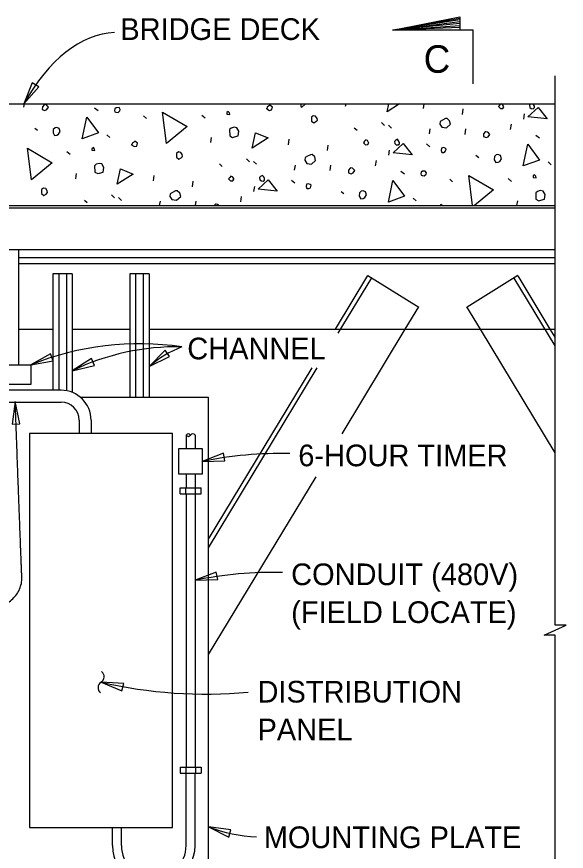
# Model space of a CAD drawing. Extents: x 927736.2 to 927809.6, y 636703.6 to 636757.7.
# Drawn here: x 927764.73 to 927774.19, y 636743.33 to 636757.7 of the extents above; entities that cross this region are included whole.
import ezdxf

# ---------------------------------------------------------------- set-up
doc = ezdxf.new("R2010")
doc.units = 0
for name, color, linetype in [('DimLines_dp', 7, 'Continuous'), ('Miscellaneous1', 7, 'Continuous'), ('Miscellaneous2', 7, 'Continuous'), ('Miscellaneous3', 7, 'Continuous')]:
    doc.layers.add(name, color=color, linetype=linetype)

msp = doc.modelspace()

# ---------------------------------------------------------------- linework, layer by layer
at = {"layer": 'DimLines_dp'}
for p, q in [((927771.201, 636757.464), (927772.357, 636757.668)), ((927772.357, 636757.643), (927771.201, 636757.464)), ((927771.201, 636757.464), (927772.357, 636757.612)), ((927772.357, 636757.578), (927771.201, 636757.464)), ((927771.201, 636757.464), (927772.357, 636757.544)), ((927772.357, 636757.507), (927771.201, 636757.464))]:
    msp.add_line(p, q, dxfattribs=at)
for points in [[(927772.589, 636756.539), (927772.589, 636757.464), (927771.201, 636757.464), (927772.357, 636757.695), (927772.357, 636757.464)], [(927774, 636737.782), (927774, 636747.055), (927773.809, 636747.055), (927774, 636747.139), (927774.191, 636747.222), (927774, 636747.222), (927774, 636756.677)]]:
    msp.add_lwpolyline(points, dxfattribs=at)
for points in [[(927764.852, 636756.193), (927765.11, 636756.486), (927764.999, 636756.555)], [(927764.974, 636751.702), (927765.359, 636751.771), (927765.315, 636751.894)], [(927767.01, 636751.678), (927767.362, 636751.848), (927767.286, 636751.954)], [(927765.688, 636751.603), (927766.068, 636751.693), (927766.018, 636751.813)], [(927764.705, 636751.071), (927764.654, 636750.684), (927764.785, 636750.688)], [(927767.924, 636750.042), (927768.314, 636750.055), (927768.288, 636750.183)], [(927767.801, 636747.996), (927768.191, 636748.009), (927768.165, 636748.137)], [(927766.183, 636746.244), (927766.543, 636746.093), (927766.573, 636746.221)], [(927768.032, 636743.756), (927768.38, 636743.579), (927768.419, 636743.703)]]:
    msp.add_lwpolyline(points, close=True, dxfattribs=at)
for centre, radius, start, end in [((927766.848, 636747.067), 5, 81.6635, 112.0069), ((927767.492, 636747.853), 4.162, 88.8828, 115.6789), ((927768.324, 636750.113), 2.043, 111.5678, 130.0212), ((927769.285, 636743.338), 6.841, 88.7814, 101.4782), ((927769.162, 636741.292), 6.841, 88.7814, 101.4782), ((927766.126, 636746.337), 0.11, 301.142, 52.8692), ((927766.24, 636746.148), 0.11, 121.142, 232.8692), ((927767.974, 636753.978), 7.939, 256.9627, 275.3449), ((927768.996, 636746.243), 2.667, 248.8193, 267.0903)]:
    msp.add_arc(centre, radius, start, end, dxfattribs=at)
msp.add_ellipse((927766.69, 636751.583), major_axis=(0.274, -5.84), ratio=0.464296, start_param=3.141604, end_param=3.781059, dxfattribs=at)
msp.add_open_spline([(927758.883, 636747.305), (927762.516, 636747.33), (927764.844, 636747.456), (927764.793, 636748.678), (927764.705, 636751.071)], degree=2, dxfattribs=at)
at = {"layer": 'Miscellaneous1'}
for p, q in [((927765.354, 636753.27), (927765.354, 636751.267)), ((927765.688, 636753.27), (927765.354, 636753.27)), ((927765.457, 636753.27), (927765.457, 636751.267)), ((927765.586, 636753.27), (927765.586, 636751.259)), ((927765.688, 636753.27), (927765.688, 636751.23)), ((927767.01, 636753.27), (927766.676, 636753.27)), ((927766.676, 636753.27), (927766.676, 636751.141)), ((927766.778, 636753.27), (927766.778, 636751.141)), ((927766.907, 636753.27), (927766.907, 636751.141)), ((927767.01, 636753.27), (927767.01, 636751.141)), ((927763.253, 636751.702), (927764.974, 636751.702)), ((927764.974, 636751.702), (927764.974, 636751.368)), ((927764.974, 636751.368), (927764.014, 636751.368)), ((927765.497, 636751.267), (927764.242, 636751.267)), ((927764.242, 636751.062), (927765.497, 636751.061)), ((927765.805, 636750.753), (927765.805, 636750.524)), ((927766.011, 636750.753), (927766.011, 636750.524)), ((927767.646, 636750.497), (927767.646, 636750.262)), ((927767.801, 636750.497), (927767.801, 636750.262)), ((927767.646, 636749.822), (927767.646, 636749.588)), ((927767.801, 636749.822), (927767.801, 636749.588)), ((927767.646, 636749.485), (927767.646, 636744.78)), ((927767.801, 636749.485), (927767.801, 636744.78)), ((927767.646, 636743.432), (927767.646, 636744.677)), ((927767.801, 636743.432), (927767.801, 636744.677)), ((927766.379, 636743.432), (927766.379, 636743.741)), ((927766.533, 636743.432), (927766.533, 636743.741))]:
    msp.add_line(p, q, dxfattribs=at)
for points in [[(927767.415, 636750.524), (927764.949, 636750.524), (927764.949, 636743.741), (927767.415, 636743.741)], [(927767.524, 636750.262), (927767.924, 636750.262), (927767.924, 636749.822), (927767.524, 636749.822)]]:
    msp.add_lwpolyline(points, close=True, dxfattribs=at)
for centre, radius, start, end in [((927765.497, 636750.753), 0.514, 0, 89.9792), ((927765.497, 636750.753), 0.308, 0, 89.9792), ((927767.685, 636750.475), 0.0441, 29.0027, 150.9974), ((927767.685, 636750.518), 0.0441, 209.003, 330.9971), ((927767.762, 636750.475), 0.0441, 29.0028, 150.9973), ((927767.09, 636743.432), 0.711, 179.9955, 0.0001), ((927767.09, 636743.432), 0.557, 180, 0)]:
    msp.add_arc(centre, radius, start, end, dxfattribs=at)
at = {"layer": 'Miscellaneous2'}
for p, q in [((927753.063, 636756.193), (927774, 636756.193)), ((927764.855, 636756.138), (927764.863, 636756.193)), ((927770.393, 636756.153), (927770.399, 636756.193)), ((927771.731, 636756.116), (927771.742, 636756.193)), ((927766.072, 636756.125), (927766.135, 636756.079)), ((927767.918, 636756.001), (927767.976, 636755.953)), ((927772.402, 636756.015), (927772.416, 636756.108)), ((927773.458, 636755.934), (927773.473, 636756.021)), ((927766.913, 636755.987), (927766.963, 636755.943)), ((927771.011, 636755.872), (927771.062, 636755.822)), ((927765.041, 636755.779), (927765.089, 636755.741)), ((927770.542, 636755.785), (927770.593, 636755.741)), ((927771.131, 636755.828), (927771.183, 636755.778)), ((927771.835, 636755.678), (927771.85, 636755.765)), ((927772.45, 636755.67), (927772.463, 636755.763)), ((927773.232, 636755.752), (927773.246, 636755.845)), ((927766.284, 636755.665), (927766.336, 636755.615)), ((927768.07, 636755.531), (927768.085, 636755.618)), ((927769.407, 636755.493), (927769.421, 636755.586)), ((927773.666, 636755.658), (927773.73, 636755.611)), ((927770.079, 636755.393), (927770.093, 636755.486)), ((927771.786, 636755.505), (927771.843, 636755.457)), ((927765.595, 636755.378), (927765.653, 636755.33)), ((927771.135, 636755.312), (927771.15, 636755.399)), ((927772.636, 636755.311), (927772.684, 636755.273)), ((927768.219, 636755.162), (927768.269, 636755.118)), ((927768.688, 636755.249), (927768.739, 636755.2)), ((927768.808, 636755.205), (927768.86, 636755.155)), ((927769.512, 636755.055), (927769.527, 636755.142)), ((927770.127, 636755.048), (927770.14, 636755.141)), ((927770.909, 636755.13), (927770.923, 636755.223)), ((927773.879, 636755.198), (927773.931, 636755.148)), ((927765.747, 636754.908), (927765.762, 636754.995)), ((927771.343, 636755.035), (927771.407, 636754.989)), ((927767.084, 636754.871), (927767.098, 636754.964)), ((927767.756, 636754.77), (927767.77, 636754.863)), ((927769.463, 636754.883), (927769.52, 636754.834)), ((927772.185, 636754.897), (927772.235, 636754.853)), ((927773.19, 636754.911), (927773.247, 636754.862)), ((927768.812, 636754.689), (927768.827, 636754.776)), ((927766.365, 636754.627), (927766.416, 636754.577)), ((927766.485, 636754.583), (927766.537, 636754.533)), ((927768.586, 636754.507), (927768.6, 636754.6)), ((927770.313, 636754.689), (927770.361, 636754.651)), ((927771.556, 636754.575), (927771.608, 636754.525)), ((927762.11, 636754.446), (927774, 636754.446)), ((927765.896, 636754.54), (927765.946, 636754.496)), ((927767.191, 636754.446), (927767.204, 636754.52)), ((927767.807, 636754.446), (927767.817, 636754.518)), ((927773.342, 636754.446), (927773.356, 636754.528)), ((927762.121, 636754.407), (927774, 636754.407)), ((927760.453, 636753.688), (927774, 636753.688))]:
    msp.add_line(p, q, dxfattribs=at)
for points in [[(927765.172, 636756.146), (927765.171, 636756.101), (927765.215, 636756.081), (927765.249, 636756.097), (927765.277, 636756.136), (927765.257, 636756.163), (927765.241, 636756.177), (927765.213, 636756.183), (927765.202, 636756.18), (927765.172, 636756.146)], [(927769.038, 636756.11), (927769.083, 636756.083), (927769.119, 636756.093), (927769.132, 636756.141), (927769.085, 636756.173), (927769.064, 636756.155), (927769.042, 636756.142), (927769.038, 636756.11), (927769.035, 636756.121)], [(927769.632, 636756.134), (927769.624, 636756.193)], [(927769.702, 636756.193), (927769.632, 636756.134)], [(927771.108, 636756.058), (927771.137, 636756.193)], [(927771.318, 636756.193), (927771.108, 636756.058)], [(927773.024, 636756.15), (927773.059, 636756.114), (927773.096, 636756.118), (927773.115, 636756.142), (927773.112, 636756.154), (927773.091, 636756.187), (927773.075, 636756.193)], [(927773.058, 636756.193), (927773.043, 636756.174), (927773.024, 636756.15)], [(927773.581, 636756.193), (927773.575, 636756.189), (927773.555, 636756.171), (927773.564, 636756.135)], [(927773.564, 636756.135), (927773.588, 636756.116), (927773.621, 636756.112), (927773.642, 636756.13), (927773.642, 636756.156), (927773.628, 636756.184), (927773.621, 636756.193)], [(927766.421, 636756.06), (927766.436, 636756.051), (927766.475, 636756.048), (927766.506, 636756.076), (927766.513, 636756.097), (927766.492, 636756.13), (927766.441, 636756.129), (927766.42, 636756.11), (927766.415, 636756.083), (927766.421, 636756.06)], [(927767.308, 636755.512), (927767.24, 636756.055), (927767.664, 636755.805), (927767.308, 636755.512)], [(927768.347, 636756.02), (927768.399, 636756.015), (927768.393, 636756.039), (927768.373, 636756.065), (927768.347, 636756.046), (927768.347, 636756.02)], [(927773.531, 636755.973), (927773.705, 636756.134), (927773.859, 636755.939), (927773.531, 636755.973)], [(927765.856, 636755.595), (927765.935, 636755.968), (927766.136, 636755.696), (927765.856, 636755.595)], [(927769.804, 636755.944), (927769.803, 636755.9), (927769.844, 636755.866), (927769.882, 636755.889), (927769.907, 636755.915), (927769.9, 636755.945), (927769.876, 636755.983), (927769.836, 636755.991), (927769.805, 636755.964), (927769.804, 636755.944)], [(927772.013, 636755.847), (927772.047, 636755.792), (927772.127, 636755.782), (927772.199, 636755.846), (927772.183, 636755.905), (927772.14, 636755.945), (927772.109, 636755.943), (927772.058, 636755.917), (927772.02, 636755.893), (927772.013, 636755.847)], [(927765.36, 636755.756), (927765.356, 636755.698), (927765.381, 636755.653), (927765.424, 636755.658), (927765.452, 636755.672), (927765.479, 636755.718), (927765.464, 636755.771), (927765.421, 636755.791), (927765.391, 636755.783), (927765.36, 636755.756)], [(927768.393, 636755.752), (927768.397, 636755.644), (927768.448, 636755.619), (927768.478, 636755.627), (927768.543, 636755.645), (927768.554, 636755.724), (927768.519, 636755.785), (927768.472, 636755.792), (927768.424, 636755.779), (927768.393, 636755.752)], [(927772.767, 636755.679), (927772.766, 636755.634), (927772.81, 636755.614), (927772.844, 636755.629), (927772.872, 636755.668), (927772.852, 636755.695), (927772.835, 636755.71), (927772.808, 636755.715), (927772.796, 636755.712), (927772.767, 636755.679)], [(927768.785, 636755.435), (927768.842, 636755.699), (927769.057, 636755.61), (927768.785, 636755.435)], [(927770.701, 636755.527), (927770.736, 636755.492), (927770.773, 636755.495), (927770.792, 636755.52), (927770.789, 636755.532), (927770.768, 636755.564), (927770.739, 636755.576), (927770.72, 636755.551), (927770.701, 636755.527)], [(927771.241, 636755.512), (927771.265, 636755.493), (927771.298, 636755.489), (927771.319, 636755.508), (927771.319, 636755.533), (927771.305, 636755.561), (927771.285, 636755.588), (927771.252, 636755.566), (927771.231, 636755.548), (927771.241, 636755.512)], [(927764.985, 636754.89), (927764.916, 636755.433), (927765.341, 636755.183), (927764.985, 636754.89)], [(927766.024, 636755.398), (927766.076, 636755.393), (927766.07, 636755.416), (927766.05, 636755.443), (927766.024, 636755.423), (927766.024, 636755.398)], [(927766.715, 636755.487), (927766.76, 636755.461), (927766.796, 636755.47), (927766.809, 636755.519), (927766.762, 636755.551), (927766.741, 636755.532), (927766.719, 636755.52), (927766.715, 636755.487), (927766.712, 636755.499)], [(927771.208, 636755.35), (927771.382, 636755.512), (927771.536, 636755.317), (927771.208, 636755.35)], [(927772.039, 636755.394), (927772.048, 636755.358), (927772.08, 636755.36), (927772.108, 636755.374), (927772.122, 636755.416), (927772.106, 636755.431), (927772.077, 636755.443), (927772.041, 636755.433), (927772.039, 636755.394)], [(927773.451, 636755.128), (927773.53, 636755.5), (927773.73, 636755.228), (927773.451, 636755.128)], [(927767.481, 636755.322), (927767.48, 636755.277), (927767.521, 636755.243), (927767.559, 636755.266), (927767.584, 636755.292), (927767.576, 636755.322), (927767.553, 636755.361), (927767.513, 636755.369), (927767.482, 636755.341), (927767.481, 636755.322)], [(927769.69, 636755.224), (927769.724, 636755.17), (927769.804, 636755.159), (927769.876, 636755.223), (927769.86, 636755.283), (927769.817, 636755.322), (927769.786, 636755.32), (927769.735, 636755.294), (927769.697, 636755.271), (927769.69, 636755.224)], [(927772.955, 636755.288), (927772.951, 636755.23), (927772.976, 636755.186), (927773.019, 636755.191), (927773.047, 636755.205), (927773.073, 636755.25), (927773.059, 636755.304), (927773.015, 636755.324), (927772.986, 636755.316), (927772.955, 636755.288)], [(927766.07, 636755.129), (927766.074, 636755.022), (927766.125, 636754.997), (927766.155, 636755.005), (927766.22, 636755.022), (927766.231, 636755.102), (927766.195, 636755.163), (927766.149, 636755.169), (927766.101, 636755.157), (927766.07, 636755.129)], [(927766.462, 636754.813), (927766.519, 636755.077), (927766.734, 636754.988), (927766.462, 636754.813)], [(927770.444, 636755.056), (927770.443, 636755.011), (927770.487, 636754.991), (927770.521, 636755.007), (927770.549, 636755.046), (927770.529, 636755.073), (927770.512, 636755.087), (927770.485, 636755.093), (927770.473, 636755.09), (927770.444, 636755.056)], [(927771.693, 636754.969), (927771.708, 636754.961), (927771.747, 636754.958), (927771.778, 636754.986), (927771.785, 636755.007), (927771.764, 636755.039), (927771.713, 636755.039), (927771.692, 636755.02), (927771.687, 636754.993), (927771.693, 636754.969)], [(927768.378, 636754.905), (927768.413, 636754.869), (927768.45, 636754.873), (927768.469, 636754.897), (927768.466, 636754.909), (927768.444, 636754.942), (927768.416, 636754.953), (927768.397, 636754.929), (927768.378, 636754.905)], [(927768.885, 636754.728), (927769.059, 636754.889), (927769.213, 636754.694), (927768.885, 636754.728)], [(927768.918, 636754.89), (927768.942, 636754.871), (927768.975, 636754.867), (927768.996, 636754.885), (927768.995, 636754.911), (927768.982, 636754.939), (927768.962, 636754.965), (927768.929, 636754.944), (927768.908, 636754.926), (927768.918, 636754.89)], [(927771.128, 636754.505), (927771.207, 636754.878), (927771.407, 636754.606), (927771.128, 636754.505)], [(927772.577, 636754.446), (927772.511, 636754.965), (927772.936, 636754.715), (927772.609, 636754.446)], [(927773.619, 636754.93), (927773.671, 636754.925), (927773.665, 636754.949), (927773.645, 636754.975), (927773.618, 636754.955), (927773.619, 636754.93)], [(927765.158, 636754.699), (927765.157, 636754.655), (927765.198, 636754.621), (927765.236, 636754.644), (927765.261, 636754.67), (927765.253, 636754.7), (927765.23, 636754.738), (927765.19, 636754.746), (927765.159, 636754.719), (927765.158, 636754.699)], [(927769.716, 636754.772), (927769.725, 636754.736), (927769.757, 636754.738), (927769.785, 636754.752), (927769.799, 636754.794), (927769.782, 636754.809), (927769.754, 636754.82), (927769.718, 636754.811), (927769.716, 636754.772)], [(927767.367, 636754.602), (927767.401, 636754.547), (927767.48, 636754.537), (927767.553, 636754.601), (927767.537, 636754.66), (927767.494, 636754.7), (927767.463, 636754.698), (927767.412, 636754.672), (927767.374, 636754.648), (927767.367, 636754.602)], [(927770.632, 636754.666), (927770.628, 636754.608), (927770.653, 636754.563), (927770.696, 636754.568), (927770.724, 636754.582), (927770.75, 636754.628), (927770.736, 636754.681), (927770.692, 636754.701), (927770.662, 636754.693), (927770.632, 636754.666)], [(927773.665, 636754.662), (927773.669, 636754.554), (927773.72, 636754.529), (927773.75, 636754.537), (927773.815, 636754.555), (927773.826, 636754.634), (927773.79, 636754.695), (927773.744, 636754.702), (927773.696, 636754.689), (927773.665, 636754.662)], [(927768.209, 636754.446), (927768.206, 636754.45), (927768.189, 636754.465), (927768.162, 636754.47), (927768.15, 636754.467), (927768.132, 636754.446)], [(927772.055, 636754.446), (927772.034, 636754.461), (927772.017, 636754.446)]]:
    msp.add_lwpolyline(points, dxfattribs=at)
at = {"layer": 'Miscellaneous3'}
for p, q in [((927764.769, 636751.702), (927764.769, 636753.688)), ((927764.769, 636753.552), (927774, 636753.552)), ((927764.769, 636753.449), (927774, 636753.449)), ((927770.219, 636752.319), (927770.777, 636753.242)), ((927770.266, 636752.248), (927770.843, 636753.201)), ((927770.777, 636753.242), (927771.65, 636752.699)), ((927773.356, 636753.242), (927772.483, 636752.699)), ((927774, 636752.029), (927773.294, 636753.197)), ((927773.915, 636752.319), (927773.36, 636753.237)), ((927771.42, 636752.319), (927771.654, 636752.704)), ((927772.713, 636752.319), (927772.48, 636752.704)), ((927764.769, 636752.319), (927765.354, 636752.319)), ((927765.688, 636752.319), (927766.676, 636752.319)), ((927767.01, 636752.319), (927774, 636752.319)), ((927770.332, 636750.519), (927771.42, 636752.319)), ((927774, 636750.191), (927772.713, 636752.319)), ((927774, 636752.178), (927773.915, 636752.319)), ((927768.032, 636748.704), (927769.816, 636751.653)), ((927768.032, 636748.555), (927769.905, 636751.652)), ((927768.032, 636746.717), (927769.883, 636749.777)), ((927767.543, 636749.588), (927767.904, 636749.588)), ((927767.543, 636749.485), (927767.543, 636749.588)), ((927767.64, 636749.485), (927767.64, 636749.588)), ((927767.807, 636749.485), (927767.807, 636749.588)), ((927767.904, 636749.485), (927767.904, 636749.588)), ((927767.543, 636749.485), (927767.904, 636749.485)), ((927767.543, 636744.78), (927767.904, 636744.78)), ((927767.543, 636744.78), (927767.543, 636744.677)), ((927767.543, 636744.677), (927767.904, 636744.677)), ((927767.64, 636744.78), (927767.64, 636744.677)), ((927767.807, 636744.78), (927767.807, 636744.677)), ((927767.904, 636744.78), (927767.904, 636744.677))]:
    msp.add_line(p, q, dxfattribs=at)
msp.add_lwpolyline([(927767.73, 636743.124), (927768.032, 636743.124), (927768.032, 636751.141), (927765.842, 636751.141)], dxfattribs=at)

# ---------------------------------------------------------------- texts
at = {"layer": 'DimLines_dp'}
for s, height, p in [('BRIDGE DECK', 0.37296, (927766.515, 636757.295)), ('C', 0.474, (927771.736, 636756.73)), ('CHANNEL', 0.373, (927767.667, 636751.799)), ('6-HOUR TIMER', 0.37296, (927769.578, 636749.959)), ('CONDUIT (480V)', 0.37296, (927769.455, 636747.913)), ('(FIELD LOCATE)', 0.37296, (927769.455, 636747.262)), ('DISTRIBUTION ', 0.37296, (927768.876, 636745.893)), ('PANEL', 0.373, (927768.876, 636745.242)), ('MOUNTING PLATE', 0.37296, (927768.984, 636743.388))]:
    msp.add_text(s, height=height, dxfattribs=at).set_placement(p)

doc.saveas('drawing.dxf')
